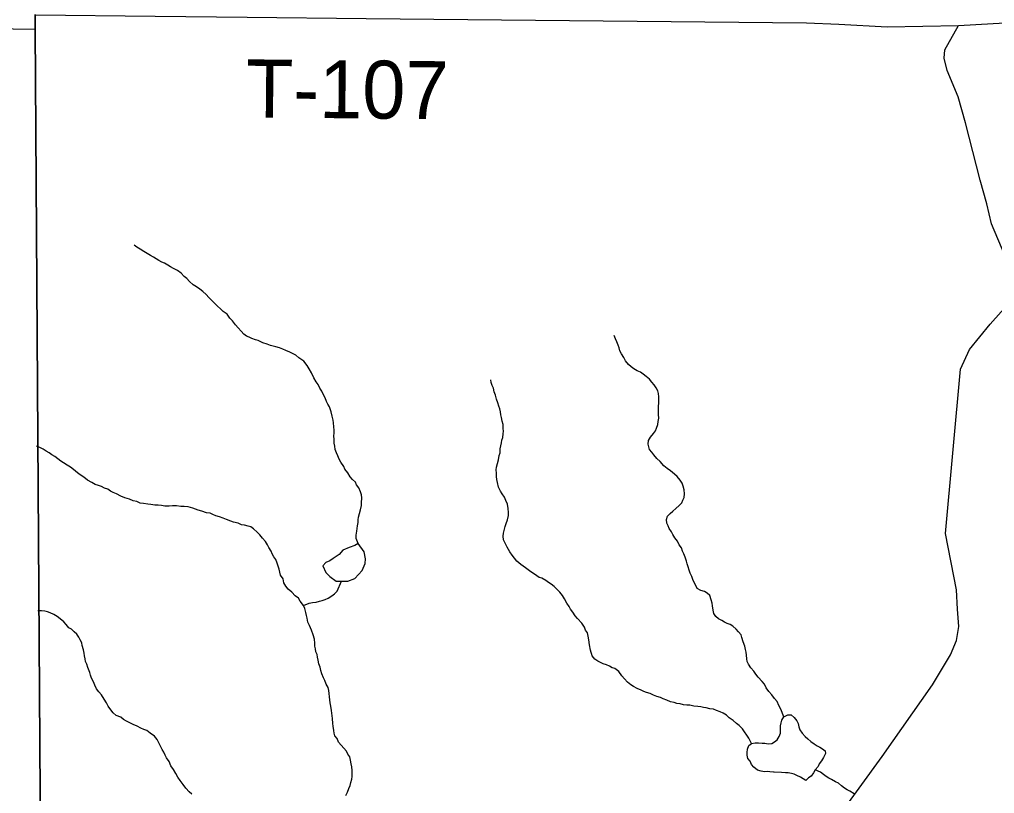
# Model space of a CAD drawing. Extents: x -7.3 to 34, y 0 to 22.
# Drawn here: x 2.725 to 3.68, y 18.947 to 19.706 of the extents above; entities that cross this region are included whole.
import ezdxf

# ---------------------------------------------------------------- set-up
doc = ezdxf.new("R2010")
doc.units = 0
for name, color, linetype in [('GM_X_Corporation', 7, 'Continuous'), ('GM_X_Minor_River', 7, 'Continuous'), ('GM_X_Township_Road', 7, 'Continuous'), ('GM_X_Township_Road_Text', 7, 'Continuous')]:
    doc.layers.add(name, color=color, linetype=linetype)

msp = doc.modelspace()

# ---------------------------------------------------------------- linework, layer by layer
at = {"layer": 'GM_X_Corporation'}
for points in [[(2.72526, 17.27857), (2.73186, 17.61235), (2.73309, 17.68446), (2.73436, 17.75863), (2.73656, 17.91355), (2.7405, 18.19145), (2.74664, 18.69646), (2.74012, 19.69659), (2.7402, 19.71066)], [(2.7402, 19.71066), (2.74012, 19.69659), (2.74664, 18.69646), (2.7405, 18.19145), (2.73656, 17.91355), (2.73436, 17.75863), (2.73309, 17.68446), (2.73186, 17.61235), (2.72526, 17.27857)], [(2.72526, 17.27857), (2.73186, 17.61235), (2.73309, 17.68446), (2.73436, 17.75863), (2.73656, 17.91355), (2.7405, 18.19145), (2.74664, 18.69646), (2.74012, 19.69659), (2.7402, 19.71066)], [(2.7402, 19.71066), (2.74012, 19.69659), (2.74664, 18.69646), (2.7405, 18.19145), (2.73656, 17.91355), (2.73436, 17.75863), (2.73309, 17.68446), (2.73186, 17.61235), (2.72526, 17.27857)]]:
    msp.add_lwpolyline(points, dxfattribs=at)
at = {"layer": 'GM_X_Minor_River'}
for points in [[(2.86422, 19.46794), (2.8616, 19.46952), (2.85898, 19.4711), (2.85636, 19.47267), (2.85336, 19.47426), (2.84998, 19.47623), (2.84661, 19.47821), (2.84325, 19.48056), (2.83988, 19.48253), (2.83727, 19.48449)], [(3.05668, 19.19205), (3.05481, 19.19702), (3.05488, 19.20044), (3.05534, 19.20423), (3.05578, 19.20688), (3.05622, 19.20953), (3.05666, 19.21256), (3.05672, 19.21523), (3.05716, 19.21787), (3.058, 19.22166), (3.05921, 19.22505), (3.06006, 19.22921), (3.06012, 19.23187), (3.06022, 19.23681), (3.05991, 19.23986), (3.05922, 19.24291), (3.05741, 19.24675), (3.05519, 19.24946), (3.05411, 19.25215), (3.05113, 19.25487), (3.04892, 19.25758), (3.04672, 19.26143), (3.04377, 19.26491), (3.04268, 19.2676), (3.03974, 19.27184), (3.03829, 19.27491), (3.03684, 19.27798), (3.03539, 19.28106), (3.03432, 19.28412), (3.03401, 19.28755), (3.03332, 19.2906), (3.03341, 19.2944), (3.03309, 19.29745), (3.03316, 19.30049), (3.03322, 19.30315), (3.03291, 19.30657), (3.03261, 19.31038), (3.03229, 19.31305), (3.03124, 19.31687), (3.03019, 19.32107), (3.02878, 19.32605), (3.02695, 19.32874), (3.02587, 19.33143), (3.02442, 19.33488), (3.0226, 19.33834), (3.02115, 19.34141), (3.01932, 19.34449), (3.0175, 19.34795), (3.01566, 19.35065), (3.01347, 19.3545), (3.01093, 19.3595), (3.00873, 19.36334), (3.0069, 19.36642), (3.00358, 19.37067), (2.99873, 19.3742), (2.99574, 19.37655), (2.99312, 19.37812), (2.98974, 19.37972), (2.98599, 19.38132), (2.98298, 19.38252), (2.97959, 19.38374), (2.9762, 19.38495), (2.97356, 19.38539), (2.97092, 19.38621), (2.96753, 19.38742), (2.96339, 19.38865), (2.95889, 19.39103), (2.95625, 19.39184), (2.95248, 19.39307), (2.94985, 19.39426), (2.94722, 19.39546), (2.94461, 19.39742), (2.94202, 19.40013), (2.93906, 19.40362), (2.93646, 19.40634), (2.93351, 19.4102), (2.93092, 19.41291), (2.92835, 19.41677), (2.92461, 19.41951), (2.92202, 19.42223), (2.91903, 19.42457), (2.91644, 19.42729), (2.91347, 19.43039), (2.91049, 19.43312), (2.90791, 19.43621), (2.90455, 19.43895), (2.90157, 19.44129), (2.89821, 19.44365), (2.89522, 19.44561), (2.89149, 19.44873), (2.8889, 19.45183), (2.88629, 19.45378), (2.88332, 19.45689), (2.87959, 19.45963), (2.87584, 19.46161), (2.87284, 19.4632), (2.87022, 19.46477), (2.86685, 19.46675), (2.86422, 19.46794)], [(3.3512, 19.32664), (3.35126, 19.32967), (3.35133, 19.33271), (3.35139, 19.33575), (3.35109, 19.33918), (3.35039, 19.34185), (3.34893, 19.34455), (3.34672, 19.34763), (3.3445, 19.35034), (3.34229, 19.35305), (3.33893, 19.35579), (3.33595, 19.35813), (3.33334, 19.36009), (3.33033, 19.36129), (3.32696, 19.36327), (3.32434, 19.36522), (3.32174, 19.36756), (3.31878, 19.37104), (3.31696, 19.37451), (3.31476, 19.37797), (3.31331, 19.38104), (3.31261, 19.38372), (3.31153, 19.3864), (3.31009, 19.38986), (3.30901, 19.39254), (3.30757, 19.39599)], [(3.19799, 19.24066), (3.19615, 19.24336), (3.19434, 19.2472), (3.1933, 19.25178), (3.19261, 19.25484), (3.1923, 19.25788), (3.19236, 19.26092), (3.19206, 19.26435), (3.19249, 19.267), (3.19333, 19.2704), (3.19417, 19.27419), (3.19502, 19.27835), (3.19583, 19.28099), (3.19591, 19.28479), (3.19674, 19.28781), (3.19718, 19.29084), (3.19762, 19.29349), (3.19844, 19.29613), (3.19889, 19.29955), (3.19933, 19.3022), (3.19901, 19.30486), (3.19871, 19.30867), (3.19803, 19.3121), (3.19734, 19.31554), (3.19664, 19.31822), (3.19633, 19.32126), (3.19563, 19.32394), (3.19455, 19.32662), (3.19348, 19.33007), (3.19242, 19.33351), (3.19137, 19.33733), (3.18993, 19.34078), (3.18924, 19.34422), (3.18816, 19.3469), (3.18709, 19.34997), (3.18677, 19.35263)], [(3.47393, 19.02218), (3.47106, 19.02984), (3.46886, 19.03331), (3.46743, 19.03715), (3.46484, 19.04024), (3.46226, 19.04372), (3.4593, 19.04721), (3.45672, 19.05068), (3.4549, 19.05415), (3.45268, 19.05685), (3.4486, 19.06112), (3.44639, 19.06421), (3.44456, 19.06691), (3.4416, 19.0704), (3.4394, 19.07387), (3.43794, 19.07656), (3.43762, 19.07923), (3.43731, 19.08266), (3.437, 19.0857), (3.4363, 19.08838), (3.43561, 19.09144), (3.43418, 19.09565), (3.43275, 19.09986), (3.43205, 19.10254), (3.42947, 19.10563), (3.42725, 19.10834), (3.42389, 19.11108), (3.42127, 19.11265), (3.41826, 19.11386), (3.41564, 19.11506), (3.41301, 19.11663), (3.41001, 19.11822), (3.40741, 19.12056), (3.4052, 19.12365), (3.40451, 19.1267), (3.40384, 19.1309), (3.40352, 19.13357), (3.40284, 19.137), (3.40141, 19.14121), (3.39881, 19.14355), (3.39618, 19.14513), (3.39241, 19.14597), (3.38904, 19.14795), (3.38686, 19.15217), (3.38504, 19.15601), (3.38361, 19.15984), (3.38216, 19.16292), (3.38109, 19.16598), (3.38002, 19.16942), (3.37932, 19.1721), (3.37862, 19.17478), (3.37719, 19.17861), (3.37575, 19.18206), (3.37467, 19.18475), (3.37359, 19.18781), (3.37139, 19.1909), (3.36956, 19.19436), (3.36698, 19.19784), (3.36515, 19.20091), (3.3637, 19.20361), (3.36149, 19.2067), (3.36041, 19.20938), (3.35933, 19.21206), (3.35902, 19.21549), (3.35986, 19.21889), (3.36257, 19.22149), (3.36527, 19.22372), (3.36798, 19.22632), (3.37146, 19.22928), (3.37379, 19.23189), (3.37499, 19.23453), (3.37618, 19.23716), (3.37665, 19.24095), (3.37635, 19.24476), (3.37529, 19.2482), (3.37421, 19.25127), (3.37238, 19.25435), (3.36943, 19.25783), (3.36682, 19.26017), (3.36272, 19.2633), (3.35973, 19.26564), (3.35638, 19.26837), (3.35268, 19.27264), (3.34932, 19.27537), (3.34636, 19.27886), (3.34453, 19.28156), (3.34231, 19.28426), (3.34161, 19.28694), (3.34091, 19.28962), (3.34136, 19.29303), (3.34333, 19.29641), (3.34606, 19.29977), (3.34801, 19.30238), (3.34921, 19.30502), (3.35043, 19.30879), (3.35087, 19.31182), (3.35132, 19.31485), (3.35102, 19.31866), (3.35108, 19.32132), (3.35114, 19.32398), (3.3512, 19.32664)], [(2.77489, 19.26695), (2.77152, 19.26893), (2.76816, 19.27128), (2.76554, 19.27286), (2.76255, 19.2752), (2.75957, 19.27755), (2.75657, 19.27913), (2.75396, 19.28109), (2.75096, 19.28268), (2.74797, 19.28464), (2.74497, 19.28623), (2.74158, 19.28744)], [(3.02736, 19.0509), (3.02554, 19.05436), (3.0241, 19.05782), (3.02264, 19.06051), (3.02121, 19.06434), (3.02014, 19.06779), (3.01945, 19.07084), (3.01839, 19.07428), (3.0177, 19.07772), (3.01701, 19.08078), (3.01669, 19.08345), (3.01523, 19.08614), (3.01491, 19.0888), (3.01421, 19.09148), (3.01428, 19.09452), (3.01398, 19.09833), (3.01255, 19.10254), (3.01114, 19.10713), (3.00896, 19.11174), (3.00752, 19.11519), (3.00684, 19.11901), (3.00614, 19.12168), (3.00544, 19.12436), (3.00439, 19.12856), (3.00331, 19.13125), (2.99999, 19.1355), (2.99816, 19.13858), (2.99518, 19.14093), (2.99184, 19.14442), (2.98812, 19.14754), (2.9859, 19.15025), (2.98408, 19.15371), (2.9834, 19.15753), (2.98082, 19.161), (2.98013, 19.16406), (2.97944, 19.16711), (2.97836, 19.1698), (2.97729, 19.17286), (2.97622, 19.1763), (2.97401, 19.17902), (2.97256, 19.18209), (2.97148, 19.18477), (2.96928, 19.18824), (2.96782, 19.19093), (2.96599, 19.19401), (2.96303, 19.1975), (2.96044, 19.20059), (2.95785, 19.20331), (2.95412, 19.20643), (2.95151, 19.20839), (2.94887, 19.20921), (2.94548, 19.21004), (2.94245, 19.21048), (2.93907, 19.21208), (2.93454, 19.21294), (2.93191, 19.21414), (2.92777, 19.21575), (2.92439, 19.21696), (2.921, 19.21817), (2.91723, 19.2194), (2.91422, 19.2206), (2.91159, 19.2218), (2.90819, 19.22225), (2.90367, 19.22387), (2.8999, 19.22471), (2.89727, 19.22591), (2.89463, 19.22673), (2.89011, 19.22797), (2.88633, 19.22843), (2.88291, 19.2285), (2.87875, 19.22897), (2.87496, 19.22905), (2.87154, 19.22875), (2.86737, 19.22884), (2.86397, 19.22929), (2.86094, 19.22974), (2.85753, 19.22981), (2.85375, 19.23028), (2.85072, 19.23072), (2.84656, 19.23119), (2.84316, 19.23165), (2.83978, 19.23324), (2.83638, 19.23407), (2.83262, 19.23567), (2.8281, 19.23691), (2.82434, 19.23852), (2.81984, 19.24089), (2.81683, 19.2421), (2.8142, 19.2433), (2.81159, 19.24526), (2.8082, 19.24647), (2.8052, 19.24805), (2.80219, 19.24888), (2.79918, 19.25008), (2.79581, 19.25206), (2.79168, 19.25405), (2.78795, 19.25717), (2.78421, 19.25953), (2.7816, 19.26149), (2.77788, 19.26461), (2.77489, 19.26695)], [(3.44226, 18.99626), (3.43972, 19.00126), (3.43751, 19.00435), (3.4353, 19.00744), (3.43347, 19.01052), (3.43012, 19.01363), (3.42751, 19.01559), (3.42417, 19.0187), (3.42043, 19.02145), (3.41783, 19.02378), (3.41446, 19.02576), (3.41146, 19.02734), (3.40807, 19.02855), (3.40506, 19.02976), (3.40128, 19.03023), (3.39788, 19.03106), (3.39524, 19.0315), (3.39259, 19.03193), (3.38957, 19.03238), (3.38578, 19.03284), (3.38163, 19.03369), (3.37898, 19.03375), (3.37557, 19.0342), (3.37218, 19.03504), (3.36915, 19.03548), (3.36652, 19.0363), (3.36274, 19.03714), (3.35936, 19.03874), (3.3556, 19.03996), (3.35297, 19.04116), (3.34958, 19.04237), (3.34619, 19.04359), (3.34281, 19.04518), (3.33942, 19.04602), (3.33679, 19.04721), (3.33416, 19.04841), (3.33002, 19.05002), (3.32665, 19.05199), (3.32403, 19.05357), (3.32068, 19.05631), (3.31771, 19.05941), (3.31512, 19.06251), (3.31218, 19.06675), (3.30844, 19.0695), (3.30581, 19.07031), (3.30318, 19.07189), (3.30018, 19.0731), (3.29679, 19.07431), (3.29416, 19.07551), (3.29153, 19.07671), (3.28854, 19.07867), (3.28596, 19.08215), (3.28456, 19.0875), (3.28354, 19.09284), (3.28289, 19.0978), (3.2822, 19.10124), (3.28152, 19.10467), (3.27968, 19.10737), (3.2786, 19.11006), (3.27603, 19.11391), (3.27158, 19.11857), (3.26936, 19.12128), (3.26716, 19.12475), (3.26495, 19.12784), (3.2635, 19.13053), (3.26129, 19.13362), (3.2591, 19.13785), (3.2569, 19.14132), (3.25431, 19.14441), (3.25172, 19.14713), (3.24874, 19.14986), (3.24576, 19.1522), (3.24314, 19.15378), (3.24053, 19.15574), (3.23678, 19.1581), (3.23415, 19.15891), (3.22966, 19.16205), (3.22592, 19.16441), (3.22331, 19.16637), (3.2207, 19.16833), (3.21621, 19.17147), (3.21212, 19.17498), (3.2099, 19.17769), (3.20769, 19.18077), (3.20548, 19.18387), (3.20293, 19.18848), (3.20073, 19.19233), (3.19929, 19.19578), (3.19899, 19.19921), (3.19905, 19.20225), (3.20027, 19.20602), (3.20071, 19.20867), (3.20191, 19.21169), (3.20313, 19.21546), (3.20398, 19.21962), (3.20405, 19.22266), (3.20375, 19.22647), (3.20308, 19.23066), (3.20164, 19.23412), (3.2002, 19.23757), (3.19799, 19.24066)], [(3.05668, 19.19205), (3.0536, 19.19023), (3.04786, 19.1881), (3.04165, 19.18563), (3.03821, 19.18151), (3.03242, 19.17747), (3.02895, 19.17528), (3.02511, 19.17348), (3.02199, 19.17014), (3.02523, 19.1636), (3.02892, 19.15971), (3.03525, 19.15537), (3.04056, 19.15524), (3.04662, 19.15509), (3.05352, 19.15795), (3.06055, 19.16575), (3.06376, 19.17251)], [(3.06376, 19.17251), (3.06388, 19.17706), (3.06254, 19.18393), (3.05668, 19.19205)], [(3.00331, 19.13125), (3.00868, 19.13379), (3.01211, 19.13448), (3.01553, 19.13478), (3.01896, 19.13547), (3.02163, 19.13617), (3.02431, 19.13725), (3.02737, 19.13871), (3.03083, 19.14091), (3.03353, 19.14275), (3.03624, 19.14536), (3.04056, 19.15524)], [(2.74983, 19.12573), (2.74642, 19.12619), (2.74301, 19.12626)], [(2.89387, 18.9466), (2.89126, 18.94894), (2.88792, 18.95244), (2.88534, 18.95591), (2.8824, 18.95978), (2.88019, 18.96325), (2.87799, 18.96672), (2.8758, 18.97057), (2.87323, 18.97442), (2.87142, 18.97864), (2.86884, 18.98212), (2.86776, 18.98481), (2.86631, 18.9875), (2.86485, 18.99019), (2.86339, 18.99289), (2.86158, 18.99673), (2.85975, 19.00019), (2.85717, 19.00328), (2.85306, 19.00641), (2.8497, 19.00877), (2.84669, 19.00998), (2.84368, 19.01118), (2.84031, 19.01316), (2.83617, 19.01477), (2.83242, 19.01675), (2.82979, 19.01795), (2.82679, 19.01953), (2.82419, 19.02187), (2.81968, 19.02348), (2.8167, 19.02621), (2.81449, 19.0293), (2.81191, 19.03278), (2.81008, 19.03586), (2.80789, 19.03971), (2.80533, 19.04394), (2.80273, 19.04666), (2.80052, 19.04975), (2.7987, 19.05321), (2.79726, 19.05666), (2.79544, 19.06012), (2.79436, 19.06319), (2.79367, 19.06586), (2.79187, 19.07047), (2.7908, 19.07391), (2.78972, 19.07659), (2.7894, 19.07926), (2.7887, 19.08194), (2.78838, 19.0846), (2.7877, 19.08804), (2.78627, 19.09225), (2.78595, 19.09492), (2.78449, 19.09761), (2.78303, 19.1003), (2.7812, 19.10339), (2.7786, 19.10572), (2.77599, 19.10806), (2.77337, 19.10964), (2.77079, 19.11273), (2.76819, 19.11545), (2.76483, 19.11818), (2.76185, 19.12053), (2.75848, 19.1225), (2.7551, 19.1241), (2.75247, 19.1253), (2.74983, 19.12573)], [(3.04479, 18.94523), (3.04639, 18.94861), (3.0476, 18.95201), (3.0488, 18.95502), (3.04962, 18.95805), (3.05045, 18.96107), (3.05089, 18.96372), (3.05096, 18.96714), (3.05102, 18.9698), (3.05071, 18.97323), (3.05002, 18.97628), (3.04934, 18.97972), (3.04865, 18.98316), (3.04681, 18.98586), (3.04536, 18.98855), (3.04277, 18.99165), (3.04017, 18.99437), (3.03758, 18.99746), (3.03614, 19.00091), (3.03392, 19.00362), (3.03322, 19.0063), (3.0329, 19.00897), (3.03223, 19.01316), (3.03191, 19.01583), (3.03164, 19.02078), (3.03099, 19.02573), (3.03067, 19.0284), (3.03, 19.0326), (3.02932, 19.03603), (3.029, 19.03908), (3.02868, 19.04175), (3.02838, 19.04518), (3.02807, 19.04823), (3.02736, 19.0509)], [(3.4644, 18.96803), (3.46365, 18.96805), (3.46025, 18.9685), (3.45759, 18.96856), (3.45493, 18.96823), (3.45154, 18.96907), (3.44814, 18.9699), (3.44442, 18.97302), (3.4422, 18.97573), (3.44075, 18.97881), (3.43853, 18.98152), (3.43784, 18.98457), (3.4379, 18.98723), (3.43835, 18.99064), (3.43956, 18.99404), (3.44226, 18.99626), (3.44569, 18.99695), (3.44911, 18.99687), (3.45251, 18.99642), (3.45516, 18.99636), (3.45857, 18.99591), (3.46199, 18.99621), (3.46467, 18.99767), (3.46738, 18.9999), (3.46934, 19.00289), (3.47055, 19.00629), (3.47062, 19.00971), (3.47071, 19.01351), (3.47115, 19.01654), (3.47197, 19.01918), (3.47393, 19.02218), (3.47777, 19.02438), (3.48118, 19.0243), (3.48416, 19.02158), (3.48675, 19.01848), (3.48783, 19.0158), (3.48851, 19.01236), (3.48959, 19.00967), (3.49179, 19.0062), (3.49476, 19.0031), (3.49736, 19.00076), (3.50034, 18.99804), (3.5037, 18.99568), (3.50669, 18.99372), (3.50932, 18.99252), (3.51194, 18.99094), (3.51455, 18.98898), (3.51487, 18.98632), (3.5129, 18.98256), (3.51093, 18.97918), (3.50858, 18.97619), (3.50739, 18.97355), (3.50466, 18.97019), (3.50309, 18.96757), (3.50074, 18.9642), (3.49804, 18.96235), (3.49533, 18.95975)], [(3.49533, 18.95975), (3.4901, 18.96329), (3.48672, 18.96488), (3.48409, 18.96608), (3.48145, 18.9669), (3.47805, 18.96735), (3.4754, 18.96741), (3.47161, 18.96787), (3.46365, 18.96805)], [(3.54285, 18.94693), (3.53873, 18.9493), (3.53611, 18.95088), (3.53348, 18.95246), (3.5305, 18.9548), (3.52752, 18.95715), (3.52452, 18.95873), (3.52077, 18.96072), (3.51815, 18.9623), (3.51553, 18.96387), (3.51291, 18.96583), (3.50993, 18.96818), (3.50466, 18.97019)]]:
    msp.add_lwpolyline(points, dxfattribs=at)
at = {"layer": 'GM_X_Township_Road'}
for p, q in [((2.74035, 19.69606), (2.74043, 19.71013)), ((2.74509, 18.9687), (2.74035, 19.69606)), ((2.74687, 18.69593), (2.74509, 18.9687))]:
    msp.add_line(p, q, dxfattribs=at)
for points in [[(2.25757, 19.70273), (2.28526, 19.70312), (2.74035, 19.69606)], [(2.74043, 19.71013), (2.85798, 19.7089), (2.94789, 19.70796), (3.0647, 19.70674), (3.49604, 19.70222), (3.52788, 19.70112), (3.57526, 19.69853), (3.64511, 19.6996), (3.76991, 19.70701), (3.80478, 19.70684)], [(3.69713, 19.45908), (3.67736, 19.5055), (3.67287, 19.52497), (3.66621, 19.5483), (3.65198, 19.60447), (3.6446, 19.62971), (3.63383, 19.65579), (3.63107, 19.66763), (3.63165, 19.67597), (3.64511, 19.6996)], [(2.74687, 18.69593), (2.83734, 18.69888), (3.18821, 18.69673), (3.25986, 18.69554), (3.29402, 18.69386), (3.3468, 18.69028), (3.36329, 18.69219), (3.3738, 18.69649), (3.38885, 18.71106), (3.39776, 18.73201), (3.41363, 18.76168), (3.50279, 18.89042), (3.57024, 18.98354), (3.61969, 19.05348), (3.63708, 19.08311), (3.6431, 19.09704), (3.64532, 19.11067), (3.6442, 19.12779), (3.64313, 19.14682), (3.63227, 19.20179), (3.64706, 19.36294), (3.65586, 19.38213), (3.67618, 19.40712), (3.6949, 19.42835)]]:
    msp.add_lwpolyline(points, dxfattribs=at)

# ---------------------------------------------------------------- texts
at = {"layer": 'GM_X_Township_Road_Text'}
msp.add_text('T-107', height=0.056818, rotation=359.43921, dxfattribs=at).set_placement((2.94657, 19.60977))

doc.saveas('drawing.dxf')
